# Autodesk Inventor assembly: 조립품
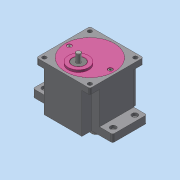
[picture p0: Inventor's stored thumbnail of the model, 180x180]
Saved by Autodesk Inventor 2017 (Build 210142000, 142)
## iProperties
Part Number: 조립품
Material: 일반
Document SubType Name: Assembly
Designer: user
Author: user
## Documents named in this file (10)
- C:\Users\user\Desktop\700116V1003\조립품.iam
- C:\Users\user\Desktop\700116V1003\메인 축.ipt
- C:\Users\user\Desktop\700116V1003\베어링 608.ipt
- C:\Users\user\Desktop\700116V1003\베어링 6003.ipt
- C:\Users\user\Desktop\700116V1003\본체.ipt
- C:\Users\user\Desktop\700116V1003\볼트 M4.ipt
- C:\Users\user\Desktop\700116V1003\서브 축.ipt
- C:\Users\user\Desktop\700116V1003\오일 실 8 22 7.ipt
- C:\Users\user\Desktop\700116V1003\오일 실 17 32 8.ipt
- C:\Users\user\Desktop\700116V1003\커버.ipt
